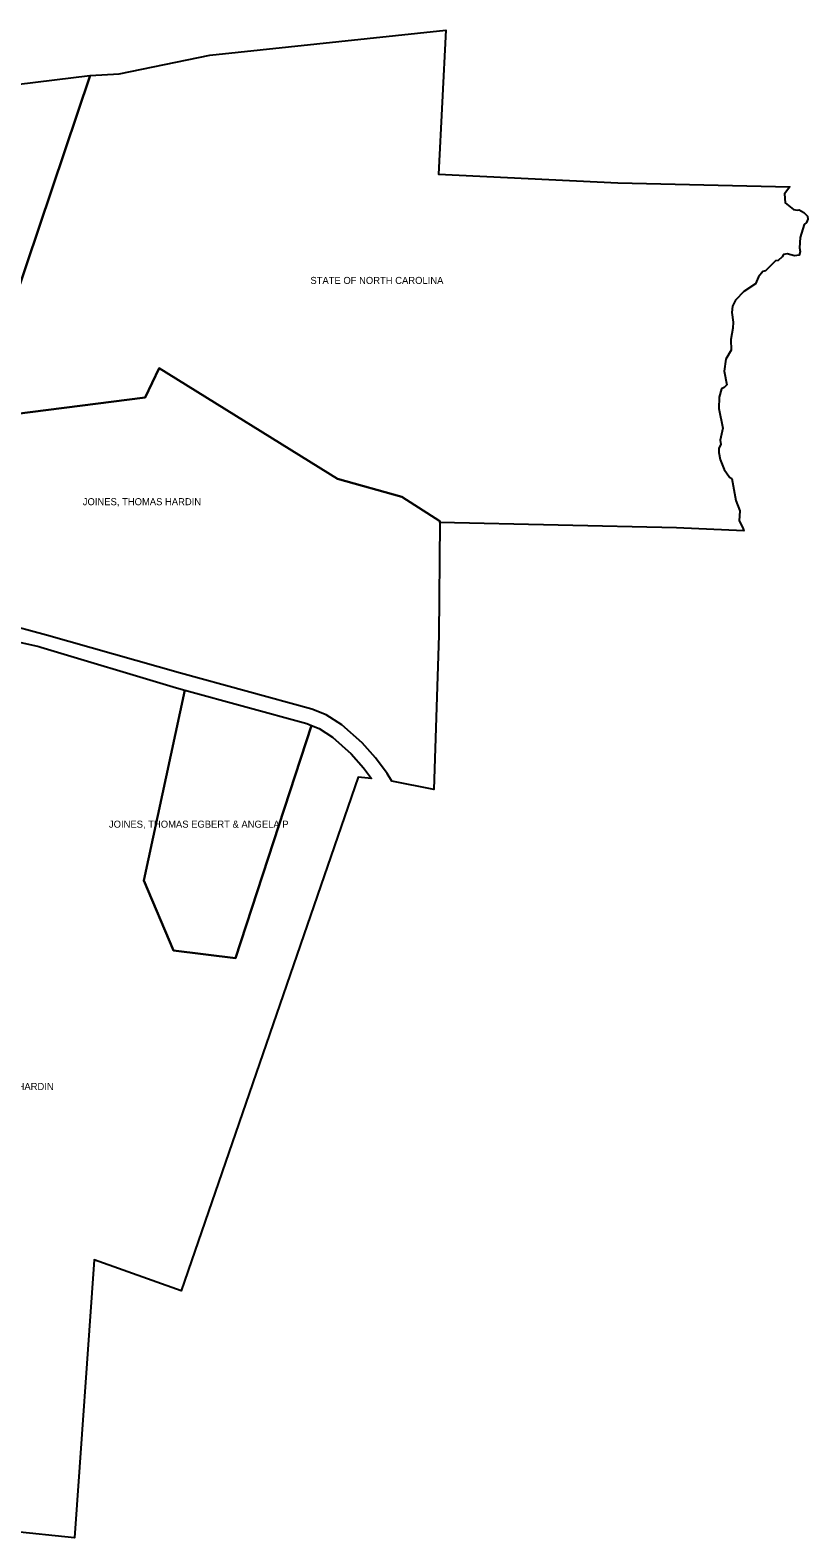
# Model space of a CAD drawing. Extents: x 1387800 to 1395118, y 956481 to 962401.
# Drawn here: x 1392086 to 1395118, y 956481 to 962358 of the extents above; entities that cross this region are included whole.
import ezdxf

# ---------------------------------------------------------------- set-up
doc = ezdxf.new("R2010")
doc.units = 0
doc.layers.add('WILKES_2010PARCELS', color=7, linetype='Continuous')

msp = doc.modelspace()

# ---------------------------------------------------------------- linework, layer by layer
at = {"layer": 'WILKES_2010PARCELS'}
for points in [[(1392022, 961296.875), (1392319.375, 962181.1875), (1392433, 962187.9375), (1392785.875, 962261.5625), (1393707, 962358.4375), (1393677.5, 961797.4375), (1394377.25, 961762.625), (1395047.125, 961747.4375), (1395027.125, 961720.625), (1395029.875, 961685.8125), (1395061.5, 961659), (1395076.75, 961656.1875), (1395084.375, 961657.8125), (1395102.375, 961647.75), (1395116, 961633.375), (1395118, 961622.1875), (1395112.75, 961608.1875), (1395103.875, 961600.5625), (1395087.875, 961549.75), (1395085.5, 961509.3125), (1395088.375, 961494.9375), (1395083.5, 961481.75), (1395066.375, 961478.125), (1395037.5, 961486.9375), (1395023.5, 961483.75), (1395018.25, 961474.5), (1395001.875, 961460.5), (1394992.25, 961459.6875), (1394953.5, 961420.5), (1394941.875, 961418.125), (1394925.5, 961396.5), (1394913.875, 961368.875), (1394868.25, 961339.6875), (1394836.25, 961306.0625), (1394823.875, 961282.875), (1394822.25, 961258.0625), (1394826.25, 961219.625), (1394825.5, 961196.4375), (1394817.875, 961152.8125), (1394819, 961110.375), (1394798.625, 961076), (1394791.375, 961029.1875), (1394801.875, 960976.3125), (1394792.25, 960965.125), (1394781, 960959.5625), (1394772.25, 960927.5), (1394771.375, 960883.5), (1394787, 960806.3125), (1394776.625, 960760.6875), (1394778.625, 960743.0625), (1394770.625, 960728.25), (1394770.625, 960711.875), (1394775.875, 960684.625), (1394791.875, 960645.8125), (1394812.25, 960615.8125), (1394821.875, 960610.625), (1394836.625, 960524.5625), (1394852.625, 960484.1875), (1394849.875, 960445.375), (1394863.875, 960418.9375), (1394867.875, 960407.25), (1394605.75, 960418.125), (1393683, 960439.3125), (1393683, 960444.1875), (1393534.625, 960538.5625), (1393284.125, 960609.4375), (1392588.625, 961040.75), (1392534.625, 960925.9375), (1391525.125, 960797.5)], [(1391544.25, 962086.75), (1392319, 962181.1875), (1392319.375, 962181.1875), (1392022, 961296.875)], [(1391525.125, 960797.5), (1392534.625, 960925.9375), (1392588.625, 961040.75), (1393284.125, 960609.4375), (1393534.625, 960538.5625), (1393683, 960444.1875), (1393683, 960439.3125), (1393678.875, 959999.75)], [(1392149.75, 960000), (1391977.375, 960046.8125)], [(1391921.5, 960000), (1392119.375, 959955.625), (1392128.125, 959953), (1392656.125, 959794), (1392688.375, 959785.1875), (1392529.25, 959044.125), (1392645, 958770.1875), (1392886.875, 958740.9375), (1393182.5, 959647.8125), (1393212.75, 959635.4375), (1393264.375, 959602.3125), (1393337.625, 959537.75), (1393385.375, 959483.3125), (1393417.125, 959441), (1393364.5, 959446.25), (1392674.75, 957444.0625), (1392335.875, 957564.125), (1392259, 956480.9375), (1392007.75, 956507)], [(1393678.875, 960000), (1393659.625, 959397.8125), (1393496.125, 959430.3125), (1393477.75, 959460), (1393432.125, 959521.1875), (1393380.125, 959580.25), (1393300.625, 959650.3125), (1393240.5, 959688.9375), (1393183.875, 959712), (1392672.625, 959851.625), (1392149.75, 960000)]]:
    msp.add_lwpolyline(points, dxfattribs=at)
msp.add_lwpolyline([(1392529.25, 959044.125), (1392688.375, 959785.1875), (1393164.625, 959655.125), (1393182.5, 959647.8125), (1392886.875, 958740.9375), (1392645, 958770.1875)], close=True, dxfattribs=at)

# ---------------------------------------------------------------- texts
for s, p in [('STATE OF NORTH CAROLINA', (1393178.460256, 961369.103254)), ('JOINES, THOMAS HARDIN', (1392291.129022, 960506.509504)), ('JOINES, THOMAS EGBERT & ANGELA P', (1392393.004633, 959249.322004)), ('JOINES, THOMAS HARDIN', (1391716.394627, 958226.728254))]:
    msp.add_text(s, height=27.480992, dxfattribs=at).set_placement(p)

doc.saveas('drawing.dxf')
